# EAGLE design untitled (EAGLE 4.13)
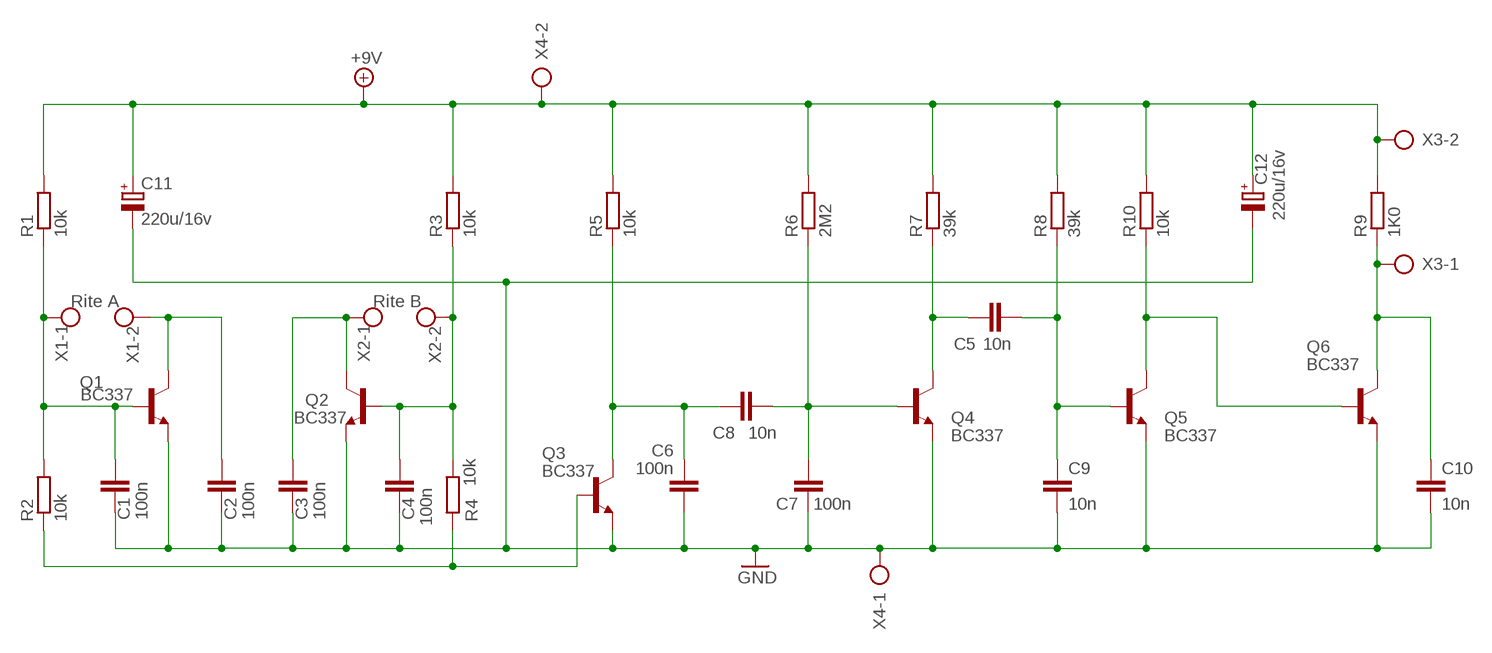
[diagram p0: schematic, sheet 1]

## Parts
C1  100n  C-EU050-030X075  [C050-030X075]
C2  100n  C-EU050-030X075  [C050-030X075]
C3  100n  C-EU050-030X075  [C050-030X075]
C4  100n  C-EU050-030X075  [C050-030X075]
C5  10n  C-EU050-030X075  [C050-030X075]
C6  100n  C-EU050-030X075  [C050-030X075]
C7  100n  C-EU050-030X075  [C050-030X075]
C8  10n  C-EU050-030X075  [C050-030X075]
C9  10n  C-EU050-030X075  [C050-030X075]
C10  10n  C-EU050-030X075  [C050-030X075]
C11  220u/16v  CPOL-EUE3.5-8  [E3,5-8]
C12  220u/16v  CPOL-EUE3.5-8  [E3,5-8]
Q1  BC337  [TO92]
Q2  BC337  [TO92]
Q3  BC337  [TO92]
Q4  BC337  [TO92]
Q5  BC337  [TO92]
Q6  BC337  [TO92]
R1  10k  R-EU_0204/7  [0204/7]
R2  10k  R-EU_0204/7  [0204/7]
R3  10k  R-EU_0204/7  [0204/7]
R4  10k  R-EU_0204/7  [0204/7]
R5  10k  R-EU_0204/7  [0204/7]
R6  2M2  R-EU_0204/7  [0204/7]
R7  39k  R-EU_0204/7  [0204/7]
R8  39k  R-EU_0204/7  [0204/7]
R9  1K0  R-EU_0204/7  [0204/7]
R10  10k  R-EU_0204/7  [0204/7]
X1  Rite A  AK500/2-H  [AK500/2-H]
X2  Rite B  AK500/2-H  [AK500/2-H]
X3  AK500/2-H  [AK500/2-H]
X4  AK500/2-H  [AK500/2-H]

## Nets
+9V: C11.+ C12.+ R1.2 R3.2 R5.2 R6.2 R7.2 R8.2 R9.2 R10.2 X3.2 X4.2
GND: C1.2 C2.2 C3.2 C4.2 C6.1 C7.1 C9.2 C10.2 C11.- C12.- Q1.1(E) Q2.1(E) Q3.1(E) Q4.1(E) Q5.1(E) Q6.1(E) X4.1
N$1: C1.1 Q1.2(B) R1.1 R2.2 X1.1
N$2: C2.1 Q1.3(C) X1.2
N$4: Q3.2(B) R2.1 R4.1
N$6: C3.1 Q2.3(C) X2.1
N$9: C4.1 Q2.2(B) R3.1 R4.2 X2.2
N$10: C6.2 C8.2 Q3.3(C) R5.1
N$11: C7.2 C8.1 Q4.2(B) R6.1
N$13: C5.1 Q4.3(C) R7.1
N$15: C5.2 C9.1 Q5.2(B) R8.1
N$18: Q5.3(C) Q6.2(B) R10.1
N$22: C10.1 Q6.3(C) R9.1 X3.1

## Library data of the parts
C1-C10 = rcl:C-EU: CAPACITOR, European symbol
C11 C12 = rcl:CPOL-EU: POLARIZED CAPACITOR, European symbol
Q1-Q6 = transistor-npn:BC337*: NPN Transistor
R1-R10 = rcl:R-EU_: RESISTOR, European symbol
X1-X4 = con-ptr500:AK500/2-H: CONNECTOR

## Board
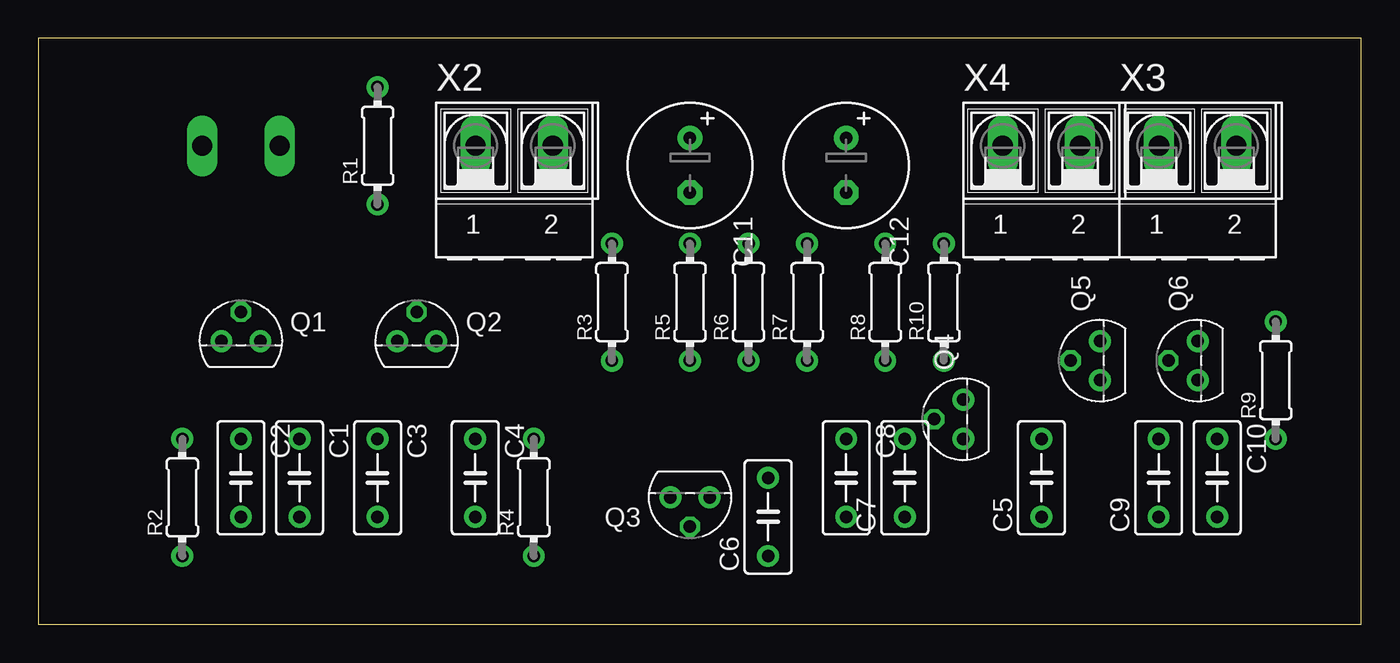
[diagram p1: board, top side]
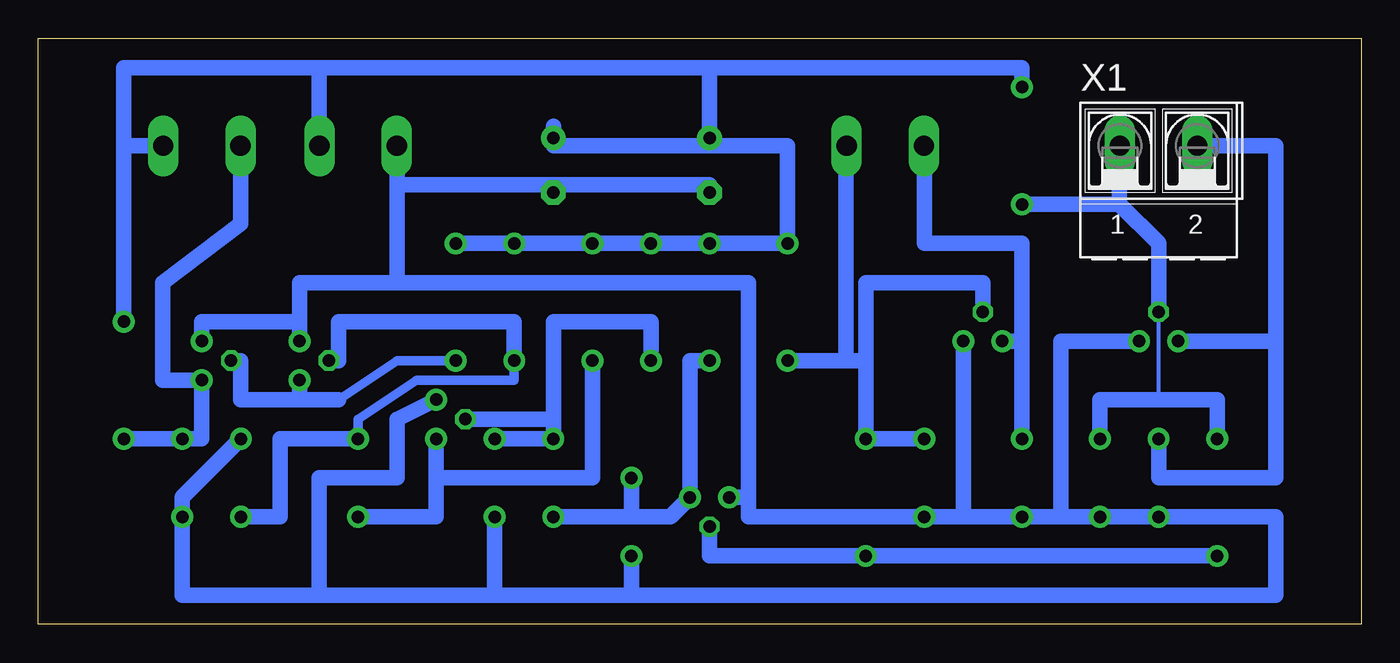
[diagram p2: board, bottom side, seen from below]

Size 86.03 x 38.09 mm. Coordinates in mm from the lower left corner, seen from the top.
Outline: 0,0 86.03,0 86.03,38.09 0,38.09 0,0
Copper layers (1*16): Top 0.035mm / dielectric 1.5mm / Bottom 0.035mm
Design rules "default": minimum track width 10mil, minimum drill 24mil, track to track 8mil, track to pad 8mil, pad to pad 8mil, via to via 8mil, smd to smd 8mil, copper to edge 40mil, drill to drill 8mil, minimum pad ring 10mil, minimum via ring 8mil, stop-mask expansion 4mil, vias tented up to drill 0mil, thermal gap 10mil

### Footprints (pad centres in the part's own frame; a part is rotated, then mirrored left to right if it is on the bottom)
C050-030X075 = drill 0.813 octagon: 1 -2.54,0; 2 2.54,0
E3,5-8 = drill 0.813 pad 1.6 round: + -1.778,0 | drill 0.813 pad 1.6 octagon: - 1.778,0
TO92 = drill 0.813 octagon: 1 1.27,0; 2 0,1.905; 3 -1.27,0
0204/7 = drill 0.813 octagon: 1 -3.81,0; 2 3.81,0
AK500/2-H = drill 1.321 long: 1 -2.515,0; 2 2.515,0

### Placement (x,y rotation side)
C1  16.98,9.52 270 top
C2  13.17,9.52 270 top
C3  22.06,9.52 270 top
C4  28.41,9.52 270 top
C5  65.24,9.52 90 top
C6  47.46,6.98 90 top
C7  56.35,9.52 90 top
C8  52.54,9.52 270 top
C9  72.86,9.52 90 top
C10  76.67,9.52 270 top
C11  42.38,29.84 270 top
C12  52.54,29.84 270 top
Q1  13.17,18.41 0 top
Q2  24.6,18.41 0 top
Q3  42.38,8.25 180 top
Q4  60.16,13.33 90 top
Q5  69.05,17.14 90 top
Q6  75.4,17.14 90 top
R1  22.06,31.11 90 top
R2  9.36,8.25 90 top
R3  37.3,20.95 90 top
R4  32.22,8.25 90 top
R5  42.38,20.95 90 top
R6  46.19,20.95 90 top
R7  50,20.95 90 top
R8  55.08,20.95 90 top
R9  80.48,15.87 90 top
R10  58.89,20.95 90 top
X1  13.17,31.11 0 bottom
X2  30.95,31.11 0 top
X3  75.4,31.11 0 top
X4  65.24,31.11 0 top

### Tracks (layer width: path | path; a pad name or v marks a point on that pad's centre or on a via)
+9V
  Bottom 0.254: R3.2 R5.2 | 52.54,31.11 C12.+
  Bottom 1.016: R10.2 R8.2 R7.2 R6.2 R5.2 R3.2 37.3,31.11 42.38,31.11 | R1.2 22.06,36.19 42.38,36.19 | 42.38,36.19 C11.+ 42.38,31.11 | 42.38,31.11 52.54,31.11 | C12.+ 52.54,32.38 | 80.48,31.11 R9.2 | 67.78,36.19 67.78,31.11 X4.2 | 42.38,36.19 67.78,36.19 | 80.48,31.11 80.48,36.19 67.78,36.19 | 80.48,31.11 X3.2
GND
  Bottom 0.254: 19.52,6.98 C3.2 25.87,6.98
  Bottom 1.016: 19.52,6.98 C1.2 C2.2 5.55,6.98 5.55,1.9 47.46,1.9 | 25.87,6.98 C4.2 39.84,6.98 39.84,8.25 | Q1.1 19.52,18.41 19.52,6.98 | 25.87,6.98 Q2.1 | 19.52,6.98 25.87,6.98 | 67.78,1.9 67.78,9.52 62.7,9.52 62.7,13.33 Q4.1 | C9.2 76.67,8.25 C10.2 76.67,1.9 67.78,1.9 | 56.35,1.9 C7.1 | 47.46,1.9 56.35,1.9 | 56.35,1.9 67.78,1.9 | 62.7,22.22 69.05,22.22 Q5.1 69.05,19.68 75.4,19.68 Q6.1 | 62.7,22.22 39.84,22.22 39.84,8.25 | 39.84,8.25 Q3.1 | 52.54,28.57 42.38,28.57 C11.- | 62.7,28.57 62.7,31.11 X4.1 | 62.7,22.22 62.7,28.57 | 62.7,28.57 52.54,28.57 | 52.54,28.57 C12.- | 47.46,1.9 C6.1
N$1
  Bottom 0.254: 13.17,14.6 Q1.2
  Bottom 1.016: 15.71,27.3 13.17,24.76 Q1.2 | 15.71,27.3 R1.1 | 15.71,27.3 15.71,29.84 X1.1 | R2.2 9.36,14.6 13.17,14.6 16.98,14.6 C1.1
N$2
  Bottom 1.016: 5.55,18.41 5.55,31.11 X1.2 | C2.1 13.17,9.52 5.55,9.52 5.55,18.41 | 5.55,18.41 Q1.3
N$3  (via drill 0.13 pad 1.42)
  other vias: 16.98,6.98
N$4
  Bottom 1.016: R2.1 R4.1 42.38,4.44 Q3.2
N$5  (via drill 0.13 pad 1.42)
  other vias: 28.41,12.06
N$6
  Bottom 1.016: C3.1 22.06,18.41 | 22.06,18.41 Q2.3 | 22.06,18.41 22.06,24.76 28.41,24.76 28.41,29.84 X2.1
N$7  (via drill 0.13 pad 1.42)
  other vias: 22.06,6.98
N$9
  Bottom 1.016: R4.2 32.22,22.22 24.6,22.22 Q2.2 | C4.1 R4.2 | R4.2 32.22,17.14 R3.1 33.49,17.14 33.49,29.84 X2.2
N$10
  Bottom 1.016: R5.1 43.65,17.14 Q3.3 44.92,6.98 47.46,6.98 | 47.46,6.98 C8.2 | 47.46,6.98 C6.2
N$11
  Bottom 1.016: 52.54,13.33 C8.1 C7.2 | 52.54,13.33 Q4.2 | R6.1 46.19,19.68 52.54,19.68 52.54,13.33
N$13
  Bottom 1.016: R7.1 50,9.52 60.16,9.52 | 60.16,9.52 Q4.3 | 60.16,9.52 60.16,6.98 C5.1
N$14  (via drill 0.13 pad 1.42)
  other vias: 32.22,4.44
N$15
  Bottom 0.61: C5.2 65.24,13.33 61.43,15.87 55.08,15.87 55.08,19.68
  Bottom 1.016: C5.2 70.32,12.06 70.32,6.98 C9.1 | R8.1 55.08,19.68 66.51,19.68 66.51,17.14 Q5.2
N$16  (via drill 0.13 pad 1.42)
  other vias: 11.9,18.41
N$17  (via drill 0.13 pad 1.42)
  other vias: 14.44,18.41
N$18
  Bottom 0.61: R10.1 62.7,17.14 66.51,14.6
  Bottom 1.016: 69.05,14.6 72.86,14.6 72.86,17.14 Q6.2 | 66.51,14.6 69.05,14.6 | 69.05,14.6 Q5.3
N$19  (via drill 0.13 pad 1.42)
  other vias: 32.22,12.06
N$20  (via drill 0.13 pad 1.42)
  other vias: 28.41,6.98
N$21  (via drill 0.13 pad 1.42)
  other vias: 22.06,12.06
N$22
  Bottom 1.016: R9.1 C10.1 75.4,12.06 Q6.3 77.94,15.87 77.94,22.22 72.86,26.03 72.86,31.11 X3.1
N$23  (via drill 0.13 pad 1.42)
  other vias: 16.98,12.06
N$24  (via drill 0.13 pad 1.42)
  other vias: 13.17,6.98
N$25  (via drill 0.13 pad 1.42)
  other vias: 13.17,12.06
N$26  (via drill 0.13 pad 1.42)
  other vias: 9.36,12.06
N$27  (via drill 0.13 pad 1.42)
  other vias: 9.36,4.44
N$28  (via drill 0.13 pad 1.42)
  other vias: 25.87,18.41
N$29  (via drill 0.13 pad 1.42)
  other vias: 23.33,18.41
N$30  (via drill 0.13 pad 1.42)
  other vias: 22.06,34.92
N$31  (via drill 0.13 pad 1.42)
  other vias: 22.06,27.3
N$32  (via drill 0.13 pad 1.42)
  other vias: 23.33,18.41
N$33  (via drill 0.13 pad 1.42)
  other vias: 25.87,18.41
N$34  (via drill 0.13 pad 1.42)
  other vias: 37.3,17.14
N$35  (via drill 0.13 pad 1.42)
  other vias: 37.3,24.76
N$36  (via drill 0.13 pad 1.42)
  other vias: 42.38,24.76
N$37  (via drill 0.13 pad 1.42)
  other vias: 42.38,17.14
N$38  (via drill 0.13 pad 1.42)
  other vias: 46.19,17.14
N$39  (via drill 0.13 pad 1.42)
  other vias: 46.19,24.76
N$40  (via drill 0.13 pad 1.42)
  other vias: 50,24.76
N$41  (via drill 0.13 pad 1.42)
  other vias: 50,17.14
N$42  (via drill 0.13 pad 1.42)
  other vias: 55.08,24.76
N$43  (via drill 0.13 pad 1.42)
  other vias: 55.08,17.14
N$44  (via drill 0.13 pad 1.42)
  other vias: 58.89,24.76
N$45  (via drill 0.13 pad 1.42)
  other vias: 58.89,17.14
N$46  (via drill 0.13 pad 1.42)
  other vias: 41.11,8.25
N$47  (via drill 0.13 pad 1.42)
  other vias: 43.65,8.25
N$48  (via drill 0.13 pad 1.42)
  other vias: 47.46,9.52
N$49  (via drill 0.13 pad 1.42)
  other vias: 47.46,4.44
N$50  (via drill 0.13 pad 1.42)
  other vias: 52.54,12.06
N$51  (via drill 0.13 pad 1.42)
  other vias: 52.54,6.98
N$52  (via drill 0.13 pad 1.42)
  other vias: 56.35,6.98
N$53  (via drill 0.13 pad 1.42)
  other vias: 56.35,12.06
N$54  (via drill 0.13 pad 1.42)
  other vias: 60.16,12.06
N$55  (via drill 0.13 pad 1.42)
  other vias: 60.16,14.6
N$56  (via drill 0.13 pad 1.42)
  other vias: 65.24,6.98
N$57  (via drill 0.13 pad 1.42)
  other vias: 65.24,12.06
N$58  (via drill 0.13 pad 1.42)
  other vias: 72.86,6.98
N$59  (via drill 0.13 pad 1.42)
  other vias: 72.86,12.06
N$60  (via drill 0.13 pad 1.42)
  other vias: 69.05,15.87
N$61  (via drill 0.13 pad 1.42)
  other vias: 69.05,18.41
N$62  (via drill 0.13 pad 1.42)
  other vias: 75.4,18.41
N$63  (via drill 0.13 pad 1.42)
  other vias: 75.4,15.87
N$64  (via drill 0.13 pad 1.42)
  other vias: 80.48,12.06
N$65  (via drill 0.13 pad 1.42)
  other vias: 80.48,19.68
N$66  (via drill 0.13 pad 1.42)
  other vias: 76.67,12.06
N$67  (via drill 0.13 pad 1.42)
  other vias: 76.67,6.98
